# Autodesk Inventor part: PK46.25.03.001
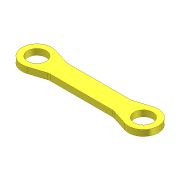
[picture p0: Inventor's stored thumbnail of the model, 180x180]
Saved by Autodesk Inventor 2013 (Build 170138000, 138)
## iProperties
Shininess: 64.0
Length Units: 11269
Angle Units: 11279
Time Units: 11290
Mass Units: 11283
Length Display Precision: 3
Angle Display Precision: 2
Compacted: True
Part Number: PK46.25.03.001
Document SubType Name: Modeling
Created: 2004-11
Material: Steel, Mild
Designer: Salex
Manufacturer: Standard
Standards Organization: Custom
Density: 7.86 g/cm^3
Density: 0.0
Volumn: 0.0
Area: 0.0
PropertySet Name: Model Information
Control State: 0
Master: False
Checked Out: False
Checked Out Date: 2008-10-15
Last Check In Date: 2008-10-15
Author: Salex
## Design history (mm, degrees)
sketch "Sketch1"
  geometry: L1 (3047.033, -1142.556)-(2332.033, -1142.556); L2 (2907.033, -1082.556)-(2472.033, -1082.556); L3 (2362.664, -1047.363)-(2472.033, -1082.556); L4 (2362.664, -1237.749)-(2472.033, -1202.556); L5 (2907.033, -1202.556)-(3016.401, -1237.749); L6 (2907.033, -1082.556)-(3016.401, -1047.363); L7 (2472.033, -1202.556)-(2907.033, -1202.556); C1 r 62.5 at (3047.033, -1142.556); C2 r 62.5 at (2332.033, -1142.556); A1 r 100 centre (3047.033, -1142.556) between (3016.401, -1237.749) and (3016.401, -1047.363); A2 r 100 centre (2332.033, -1142.556) between (2362.664, -1047.363) and (2362.664, -1237.749)
  constraints: 14 end point, 4 centre point, 4 point on circle, 4 tangent, 3 equal length, 3 parallel, 2 coincident, 2 equal radius, 1 other
  dimensions: "d0" = 0 vertical distance of L1.end L1.start; "d1" = 715 distance of L1.end L1.start; "d2" = 200 diameter of A1; "d3" = 60 distance between parallel lines of L1 L2; "d5" = 125 diameter of C1; "d9" = 140 horizontal distance of L2.end L1.end
extrude "Extrusion1" new body sketch "Sketch1" distance "d6" = 40; taper "d7" = 0 deg
fillet "Fillet1" dims "d8" = 50
workplane "Work Plane1"
workaxis "Work Axis1"
workaxis "Work Axis2"
body "Solid1"
